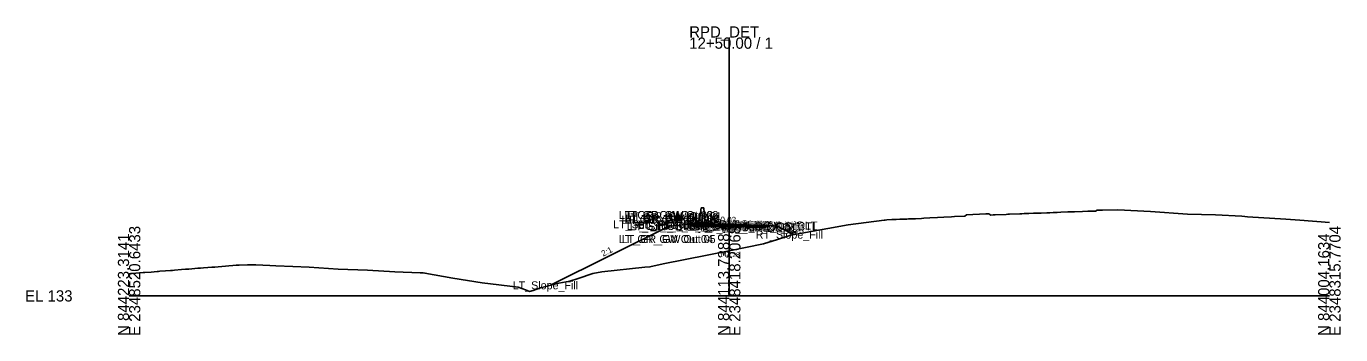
# Model space of a CAD drawing. Extents: x -26 to 2348503, y -10 to 844218.
# Drawn here: x -25.7 to 302.8, y 2490.3 to 2567.4 of the extents above; entities that cross this region are included whole.
import ezdxf

# ---------------------------------------------------------------- set-up
doc = ezdxf.new("R2010")
doc.units = 0
for name, color, linetype in [('Default', 7, 'Continuous'), ('Exist Cross Section Cell', 7, 'Continuous'), ('Exist XS Center Line Elevation Label', 7, 'Continuous'), ('Exist XS Ground Line', 7, 'Continuous'), ('Old_Level_1', 7, 'Continuous'), ('Prop CMT Pvmt Course 1', 7, 'Continuous'), ('Prop CMT Pvmt Course 2', 7, 'Continuous'), ('Prop CMT Pvmt Course 3', 7, 'Continuous'), ('Prop CMT Pvmt Surface', 7, 'Continuous'), ('Prop CMT Pvmt Surface Shoulder', 7, 'Continuous'), ('Prop CMT Shld Paved Course 1', 7, 'Continuous'), ('Prop CMT Shld Paved Course 2', 7, 'Continuous'), ('Prop CMT Shld Paved Course 3', 7, 'Continuous'), ('Prop CMT Slope Grass', 7, 'Continuous'), ('Prop CMT Subgrade Earthwork', 7, 'Continuous'), ('Prop XS Earthwork Shape', 7, 'Continuous'), ('Prop XS SE Text', 7, 'Continuous'), ('Typical Median Barrier CELL', 7, 'Continuous')]:
    doc.layers.add(name, color=color, linetype=linetype)

# ---------------------------------------------------------------- blocks, each defined once
blk = doc.blocks.new('TYPE T DOUBLE FACE BARRIER')
at = {"layer": 'Typical Median Barrier CELL'}
for p, q in [((-0.33, 3.83), (-0.6, 1.3)), ((0, 3.83), (-0.33, 3.83)), ((0, 3.83), (0.33, 3.83)), ((0.33, 3.83), (0.6, 1.3)), ((-0.75, 0.91), (-1.21, 0.25)), ((-1.21, -0.17), (-1.21, 0.25)), ((0, 0), (0, 0)), ((0.75, 0.91), (1.21, 0.25)), ((1.21, -0.17), (1.21, 0.25)), ((-1.21, -0.17), (1.21, -0.17))]:
    blk.add_line(p, q, dxfattribs=at)
for centre, start, end in [((-1.43, 1.38), 325.0039, 353.9447), ((1.43, 1.38), 186.0553, 214.9937)]:
    blk.add_arc(centre, 0.833, start, end, dxfattribs=at)

msp = doc.modelspace()

# ---------------------------------------------------------------- linework, layer by layer
at = {"layer": 'Exist Cross Section Cell'}
for p, q in [((150, 2500), (150, 2564.55)), ((0, 2500), (150, 2500)), ((150, 2500), (300, 2500))]:
    msp.add_line(p, q, dxfattribs=at)
at = {"layer": 'Exist XS Ground Line'}
msp.add_lwpolyline([(0, 2505.54), (0.35, 2505.57), (0.81, 2505.63), (3.55, 2505.82), (3.96, 2505.85), (5.54, 2505.97), (7, 2506.09), (7.32, 2506.11), (7.67, 2506.14), (9.1, 2506.25), (10.37, 2506.35), (10.84, 2506.38), (11.34, 2506.42), (13.13, 2506.58), (14.11, 2506.67), (14.43, 2506.67), (14.95, 2506.7), (17.22, 2506.89), (17.88, 2506.94), (18.6, 2507), (19.68, 2507.09), (20.68, 2507.17), (21.44, 2507.22), (22.28, 2507.29), (24.09, 2507.43), (24.95, 2507.5), (25.95, 2507.57), (26.79, 2507.64), (27.52, 2507.68), (29.63, 2507.78), (30.35, 2507.78), (31.72, 2507.77), (35.21, 2507.63), (36.7, 2507.52), (40.95, 2507.36), (45.05, 2507.15), (52.24, 2506.71), (59.56, 2506.39), (66.39, 2506), (72.78, 2505.8), (73.47, 2505.75), (73.94, 2505.69), (80.92, 2504.46), (88.28, 2503.3), (97.23, 2502.19), (99.09, 2501.48), (100.12, 2501.13), (101.04, 2501.32), (102.82, 2501.99), (107.44, 2503.17), (110.17, 2503.72), (112.22, 2504.34), (115.92, 2505.57), (118.13, 2505.98), (128.87, 2507.18), (130.18, 2507.26), (133.53, 2507.98), (150, 2511.28), (158.55, 2513), (162.03, 2514.11), (165.44, 2515.18), (179.69, 2517.72), (188.69, 2518.93), (189.01, 2518.96), (189.39, 2518.98), (190.62, 2519.05), (191.3, 2519.09), (191.69, 2519.11), (192.61, 2519.15), (194.39, 2519.21), (194.82, 2519.22), (195.23, 2519.24), (196.6, 2519.29), (198.04, 2519.36), (198.67, 2519.39), (200.13, 2519.47), (202.09, 2519.57), (203.68, 2519.65), (205.53, 2519.75), (206.34, 2519.8), (208.93, 2519.91), (209.31, 2520.29), (214.12, 2520.5), (214.91, 2520.54), (215.35, 2520.21), (216, 2520.23), (216.47, 2520.25), (219.19, 2520.36), (219.6, 2520.38), (220.02, 2520.4), (222.62, 2520.51), (223.12, 2520.54), (223.68, 2520.55), (224.91, 2520.59), (226.04, 2520.63), (226.79, 2520.66), (227.14, 2520.67), (227.98, 2520.7), (229.42, 2520.76), (230.15, 2520.79), (230.93, 2520.83), (231.96, 2520.87), (232.88, 2520.91), (234.63, 2520.98), (235.47, 2521.01), (236.28, 2521.04), (238.29, 2521.12), (239.67, 2521.16), (240.76, 2521.18), (241.57, 2521.18), (242, 2521.43), (243.3, 2521.46), (247.13, 2521.52), (255.33, 2521.05), (264.57, 2520.42), (271.57, 2520.23), (278.12, 2519.89), (278.87, 2519.84), (279.52, 2519.79), (289.09, 2519.14), (292.66, 2518.89), (300, 2518.36)], dxfattribs=at)
at = {"layer": 'Prop CMT Pvmt Course 1'}
for p, q in [((150, 2517.86), (142, 2518.02)), ((142, 2518.02), (142, 2517.77)), ((142, 2517.77), (150, 2517.61)), ((150, 2517.61), (150, 2517.86)), ((150, 2517.86), (158, 2517.7)), ((150, 2517.61), (150, 2517.86)), ((150, 2517.61), (150, 2517.73)), ((150, 2517.73), (150, 2517.73)), ((150, 2517.73), (150, 2517.61)), ((150, 2517.61), (150, 2517.73)), ((150, 2517.73), (150, 2517.73)), ((150, 2517.73), (150, 2517.61)), ((150, 2517.61), (150, 2517.61)), ((158, 2517.45), (150, 2517.61)), ((150, 2517.61), (150, 2517.61)), ((158, 2517.7), (158, 2517.45))]:
    msp.add_line(p, q, dxfattribs=at)
at = {"layer": 'Prop CMT Pvmt Course 2'}
for p, q in [((142, 2517.77), (150, 2517.61)), ((150, 2517.61), (142, 2517.77)), ((142, 2517.77), (142, 2517.77)), ((150, 2517.61), (150, 2517.61)), ((158, 2517.45), (150, 2517.61)), ((150, 2517.61), (150, 2517.61)), ((150, 2517.61), (158, 2517.45)), ((158, 2517.45), (158, 2517.45))]:
    msp.add_line(p, q, dxfattribs=at)
at = {"layer": 'Prop CMT Pvmt Course 3'}
for p, q in [((150, 2517.61), (142, 2517.77)), ((142, 2517.77), (142, 2517.44)), ((142, 2517.44), (150, 2517.28)), ((150, 2517.28), (150, 2517.61)), ((150, 2517.61), (158, 2517.45)), ((150, 2517.28), (150, 2517.61)), ((158, 2517.12), (150, 2517.28)), ((158, 2517.45), (158, 2517.12))]:
    msp.add_line(p, q, dxfattribs=at)
at = {"layer": 'Prop CMT Pvmt Surface'}
for q in [(142, 2518.02), (158, 2517.7)]:
    msp.add_line((150, 2517.86), q, dxfattribs=at)
at = {"layer": 'Prop CMT Pvmt Surface Shoulder'}
for p, q in [((142, 2518.02), (142, 2518.02)), ((158, 2517.7), (158, 2517.7))]:
    msp.add_line(p, q, dxfattribs=at)
at = {"layer": 'Prop CMT Shld Paved Course 1'}
for p, q in [((142, 2518.02), (141.74, 2517.76)), ((141.74, 2517.76), (142, 2517.77)), ((142, 2518.02), (142, 2518.02)), ((142, 2517.77), (142, 2518.02)), ((158, 2517.7), (158, 2517.7)), ((158, 2517.7), (158.26, 2517.44)), ((158, 2517.45), (158, 2517.7)), ((158.26, 2517.44), (158, 2517.45))]:
    msp.add_line(p, q, dxfattribs=at)
at = {"layer": 'Prop CMT Shld Paved Course 2'}
for p, q in [((142, 2517.77), (141.74, 2517.76)), ((141.74, 2517.76), (142, 2517.77)), ((141.74, 2517.76), (141.74, 2517.76)), ((142, 2517.77), (142, 2517.77)), ((158, 2517.45), (158.26, 2517.44)), ((158.26, 2517.44), (158, 2517.45)), ((158, 2517.45), (158, 2517.45)), ((158.26, 2517.44), (158.26, 2517.44))]:
    msp.add_line(p, q, dxfattribs=at)
at = {"layer": 'Prop CMT Shld Paved Course 3'}
for p, q in [((141.24, 2517.75), (140.9, 2517.41)), ((140.9, 2517.41), (142, 2517.44)), ((141.74, 2517.76), (141.24, 2517.75)), ((142, 2517.77), (141.74, 2517.76)), ((142, 2517.44), (142, 2517.77)), ((158, 2517.45), (158.26, 2517.44)), ((158, 2517.12), (158, 2517.45)), ((159.1, 2517.09), (158, 2517.12)), ((158.26, 2517.44), (158.76, 2517.43)), ((158.76, 2517.43), (159.1, 2517.09))]:
    msp.add_line(p, q, dxfattribs=at)
at = {"layer": 'Prop CMT Slope Grass'}
for p, q in [((135, 2517.46), (105.37, 2502.65)), ((142, 2518.02), (135, 2517.46)), ((158, 2517.7), (162, 2517.38)), ((162, 2517.38), (166.15, 2515.31))]:
    msp.add_line(p, q, dxfattribs=at)
at = {"layer": 'Prop CMT Subgrade Earthwork'}
for p, q in [((140.9, 2517.41), (140.43, 2517.89)), ((142, 2517.44), (140.9, 2517.41)), ((150, 2517.28), (142, 2517.44)), ((150, 2517.28), (158, 2517.12)), ((158, 2517.12), (159.1, 2517.09)), ((159.1, 2517.09), (159.57, 2517.57))]:
    msp.add_line(p, q, dxfattribs=at)
at = {"layer": 'Prop XS Earthwork Shape'}
msp.add_lwpolyline([(105.37, 2502.65), (107.44, 2503.17), (110.17, 2503.72), (112.22, 2504.34), (115.92, 2505.57), (118.13, 2505.98), (128.87, 2507.18), (130.18, 2507.26), (133.53, 2507.98), (150, 2511.28), (158.55, 2513), (162.03, 2514.11), (165.44, 2515.18), (166.15, 2515.31), (162, 2517.38), (159.57, 2517.57), (159.1, 2517.09), (158, 2517.12), (150, 2517.28), (142, 2517.44), (140.9, 2517.41), (140.43, 2517.89), (135, 2517.46)], close=True, dxfattribs=at)

# ---------------------------------------------------------------- block references
at = {"layer": 'Old_Level_1', "yscale": -0.9999999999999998, "rotation": 178.85423716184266}
msp.add_blockref('TYPE T DOUBLE FACE BARRIER', (143.21, 2518.16), dxfattribs=at)

# ---------------------------------------------------------------- texts
at = {"layer": 'Default'}
for s, height, p in [('LT_GR_GW Out 03', 2, (122.44, 2519.2)), ('LT_GR_GW Out 06', 2, (123.06, 2518.03)), ('LT_GR_GW Out 02', 2, (123.78, 2519.2)), ('LT_GR_GW Out 09', 2, (123.78, 2518.62)), ('LT_GR_GW Out 07', 2, (123.78, 2518.03)), ('LT_GR_GW Out 08', 2, (124.05, 2518.32)), ('LT_GR_GW Out 01', 2, (124.61, 2518.91)), ('LT_Sub_Trench_Out_DLT', 2, (120.99, 2516.89)), ('LT_GS_OS_CTL', 2, (124.37, 2516.46)), ('LT_Sub_Trench_Out', 2, (125.11, 2516.41)), ('LT_PS3_Shelf_Out', 2, (127.23, 2516.75)), ('LT_PS3_OEOP', 2, (131.98, 2516.76)), ('LT_PS2_OEOP', 2, (131.98, 2516.76)), ('LT_Sub_OEOT', 2, (132.08, 2516.44)), ('LT_PV3_OEOT', 2, (132.17, 2516.77)), ('LT_PV2_OEOT', 2, (132.17, 2516.77)), ('LT_PV1_OEOT', 2, (132.74, 2517.02)), ('LT_PS1_OEOP', 2, (132.8, 2517.02)), ('RT_Sub_OEEOP', 2, (139.17, 2516.28)), ('LT_Sub_OEEOP', 2, (139.21, 2516.28)), ('RT_PV2_OEEOP', 2, (139.26, 2516.61)), ('RT_PV3_OEEOP', 2, (139.26, 2516.61)), ('LT_PV2_OEEOP', 2, (139.31, 2516.61)), ('LT_PV3_OEEOP', 2, (139.31, 2516.61)), ('RT_PV1_OEEOP', 2, (139.83, 2516.73)), ('LT_PV1_OEEOP', 2, (139.87, 2516.73)), ('RT_PV2_IEEOP', 2, (139.91, 2516.61)), ('LT_PV2_IEEOP', 2, (139.95, 2516.61)), ('RT_Sub_Trench_Out_DLT', 2, (140.09, 2516.57)), ('RT_PV1_IEEOP', 2, (140.47, 2516.73)), ('LT_PV1_IEEOP', 2, (140.52, 2516.73)), ('RT_Sub_Trench_Out', 2, (143.25, 2516.09)), ('PV2_PGL', 2, (143.91, 2516.61)), ('PV1_PGL', 2, (144.47, 2516.86)), ('RT_PS3_Shelf_Out', 2, (144.69, 2516.43)), ('RT_Sub_OEOT', 2, (148.03, 2516.12)), ('RT_PV3_OEOT', 2, (148.13, 2516.45)), ('RT_PV2_OEOT', 2, (148.13, 2516.45)), ('RT_PS3_OEOP', 2, (148.44, 2516.44)), ('RT_PS2_OEOP', 2, (148.44, 2516.44)), ('RT_PV1_OEOT', 2, (148.69, 2516.7)), ('RT_PS1_OEOP', 2, (148.76, 2516.7)), ('RT_GS_OS_CTL', 2, (151.32, 2516.38)), ('LT_GR_GW Out 04', 2, (122.44, 2513.2)), ('LT_GR_GW Out 05', 2, (123.11, 2513.2)), ('RT_Slope_Fill', 2, (156.62, 2514.31)), ('LT_Slope_Fill', 2, (95.89, 2501.65)), ('-', 0.0001, (0, 2500))]:
    msp.add_text(s, height=height, dxfattribs=at).set_placement(p)
at = {"layer": 'Exist Cross Section Cell'}
for s, p in [('RPD_DET', (140, 2564.55)), ('12+50.00 / 1', (140, 2561.75)), ('EL 133', (-26, 2498.6))]:
    msp.add_text(s, height=2.8, dxfattribs=at).set_placement(p)
for s, p in [('E 2348520.6433', (2.8, 2490)), ('E 2348418.2068', (152.8, 2490)), ('E 2348315.7704', (302.8, 2490)), ('N 844223.3141', (0, 2490)), ('N 844113.7388', (150, 2490)), ('N 844004.1634', (300, 2490))]:
    msp.add_text(s, height=2.8, rotation=90, dxfattribs=at).set_placement(p)
at = {"layer": 'Exist XS Center Line Elevation Label'}
msp.add_text('144.28', height=1.2, dxfattribs=at).set_placement((147.55, 2509.68))
at = {"layer": 'Prop XS SE Text'}
for s, rotation, p in [('0.02', 358.8542, (147.79, 2518.32)), ('2:1', 333.4349, (163.3, 2517.19)), ('2:1', 26.5651, (118.5, 2509.79))]:
    msp.add_text(s, height=1.5, rotation=rotation, dxfattribs=at).set_placement(p)

doc.saveas('drawing.dxf')
